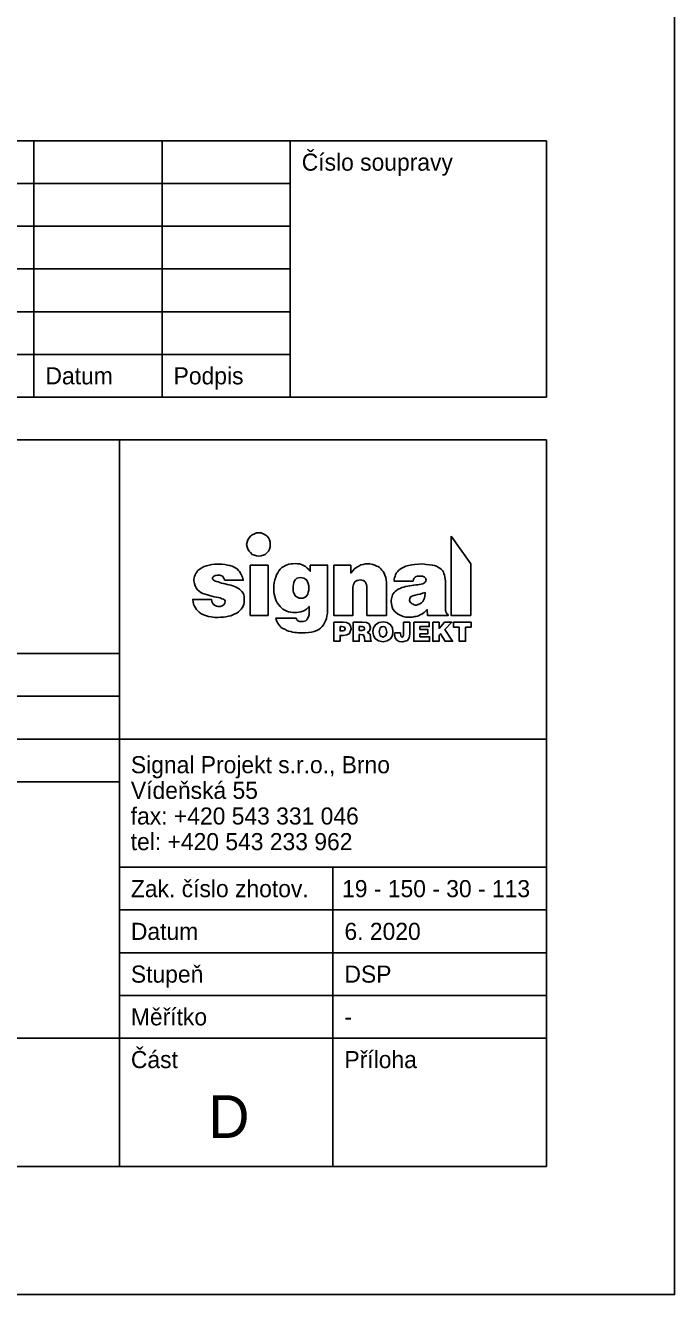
# Model space of a CAD drawing. Extents: x -790471 to -790261, y -985854 to -985557.
# Drawn here: x -790336.6 to -790260.6, y -985853.6 to -985705.1 of the extents above; entities that cross this region are included whole.
import ezdxf

# ---------------------------------------------------------------- set-up
doc = ezdxf.new("R2010")
doc.units = 0
for name, color, linetype in [('Info o rozpiskách', 7, 'Continuous'), ('popis', 7, 'Continuous'), ('Ramečky', 7, 'Continuous'), ('Rámečky-tisk', 7, 'Continuous'), ('Text', 7, 'Continuous'), ('Text barevný', 7, 'Continuous')]:
    doc.layers.add(name, color=color, linetype=linetype)

msp = doc.modelspace()

# ---------------------------------------------------------------- linework, layer by layer
at = {"layer": 'Info o rozpiskách'}
for points in [[(-790309.25, -985764.46), (-790308.98, -985764.47), (-790308.76, -985764.57), (-790308.54, -985764.7), (-790308.29, -985764.87), (-790308.15, -985765.07), (-790308.03, -985765.31), (-790307.94, -985765.58), (-790307.92, -985765.84), (-790307.94, -985766.1), (-790308.03, -985766.38), (-790308.15, -985766.62), (-790308.29, -985766.79), (-790308.54, -985766.99), (-790308.76, -985767.09), (-790308.98, -985767.18), (-790309.25, -985767.2), (-790309.54, -985767.18), (-790309.79, -985767.09), (-790310.05, -985766.99), (-790310.23, -985766.79), (-790310.4, -985766.62), (-790310.57, -985766.38), (-790310.65, -985766.1), (-790310.7, -985765.84), (-790310.65, -985765.58), (-790310.57, -985765.31), (-790310.4, -985765.07), (-790310.23, -985764.87), (-790310.05, -985764.7), (-790309.79, -985764.57), (-790309.54, -985764.47), (-790309.25, -985764.46)], [(-790300.48, -985774.94), (-790299.41, -985774.94), (-790299, -985774.98), (-790298.7, -985775.13), (-790298.52, -985775.37), (-790298.46, -985775.72), (-790298.65, -985776.25), (-790298.95, -985776.42), (-790299.38, -985776.47), (-790299.75, -985776.47), (-790299.75, -985777.16), (-790300.48, -985777.16), (-790300.48, -985774.94)], [(-790299.75, -985775.44), (-790299.75, -985775.95), (-790299.43, -985775.95), (-790299.25, -985775.89), (-790299.15, -985775.69), (-790299.23, -985775.52), (-790299.54, -985775.44), (-790299.75, -985775.44)], [(-790298.24, -985774.94), (-790297.16, -985774.94), (-790296.67, -985774.98), (-790296.35, -985775.13), (-790296.19, -985775.58), (-790296.3, -985775.93), (-790296.56, -985776.12), (-790296.24, -985776.34), (-790296.19, -985776.71), (-790296.19, -985776.88), (-790296.17, -985777.05), (-790296.11, -985777.11), (-790296.11, -985777.16), (-790296.86, -985777.16), (-790296.9, -985776.77), (-790297.03, -985776.42), (-790297.18, -985776.4), (-790297.4, -985776.38), (-790297.51, -985776.38), (-790297.51, -985777.16), (-790298.24, -985777.16), (-790298.24, -985774.94)], [(-790297.51, -985775.44), (-790297.51, -985775.89), (-790297.19, -985775.89), (-790296.93, -985775.82), (-790296.88, -985775.69), (-790296.95, -985775.52), (-790297.16, -985775.44), (-790297.51, -985775.44)], [(-790294.73, -985774.89), (-790294.23, -985774.96), (-790293.84, -985775.22), (-790293.63, -985775.59), (-790293.56, -985776.02), (-790293.63, -985776.49), (-790293.85, -985776.86), (-790294.23, -985777.12), (-790294.73, -985777.22), (-790295.25, -985777.12), (-790295.65, -985776.84), (-790295.83, -985776.47), (-790295.91, -985776.02), (-790295.83, -985775.58), (-790295.61, -985775.22), (-790295.23, -985774.96), (-790294.73, -985774.89)], [(-790294.73, -985775.43), (-790294.92, -985775.46), (-790295.05, -985775.58), (-790295.16, -985776.04), (-790295.05, -985776.53), (-790294.73, -985776.68), (-790294.38, -985776.49), (-790294.28, -985776.08), (-790294.4, -985775.61), (-790294.53, -985775.46), (-790294.73, -985775.43)], [(-790292.33, -985774.94), (-790291.6, -985774.94), (-790291.6, -985776.32), (-790291.67, -985776.75), (-790291.88, -985777.05), (-790292.46, -985777.22), (-790292.83, -985777.18), (-790293.11, -985777.03), (-790293.29, -985776.75), (-790293.37, -985776.36), (-790293.35, -985776.19), (-790292.7, -985776.19), (-790292.66, -985776.56), (-790292.51, -985776.68), (-790292.38, -985776.6), (-790292.33, -985776.42), (-790292.33, -985774.94)], [(-790291.13, -985774.94), (-790289.32, -985774.94), (-790289.32, -985775.44), (-790290.4, -985775.44), (-790290.4, -985775.78), (-790289.49, -985775.78), (-790289.49, -985776.3), (-790290.4, -985776.3), (-790290.4, -985776.64), (-790289.27, -985776.64), (-790289.27, -985777.16), (-790291.13, -985777.16), (-790291.13, -985774.94)], [(-790288.91, -985774.94), (-790288.16, -985774.94), (-790288.16, -985775.65), (-790287.53, -985774.94), (-790286.67, -985774.94), (-790287.49, -985775.78), (-790286.58, -985777.16), (-790287.46, -985777.16), (-790288, -985776.28), (-790288.16, -985776.45), (-790288.16, -985777.16), (-790288.91, -985777.16), (-790288.91, -985774.94)], [(-790286.47, -985774.94), (-790284.41, -985774.94), (-790284.41, -985775.52), (-790285.07, -985775.52), (-790285.07, -985777.16), (-790285.8, -985777.16), (-790285.8, -985775.52), (-790286.47, -985775.52), (-790286.47, -985774.94)]]:
    msp.add_lwpolyline(points, dxfattribs=at)
at = {"layer": 'popis'}
for points in [[(-790286.77, -985764.87), (-790286.77, -985774.14), (-790284.45, -985774.14), (-790284.45, -985768.11), (-790286.77, -985764.87)], [(-790313.29, -985770.02), (-790311.09, -985770.02), (-790311.15, -985769.83), (-790311.19, -985769.66), (-790311.24, -985769.49), (-790311.32, -985769.33), (-790311.41, -985769.18), (-790311.52, -985769.01), (-790311.63, -985768.86), (-790311.8, -985768.69), (-790311.97, -985768.6), (-790312.17, -985768.49), (-790312.4, -985768.39), (-790312.66, -985768.3), (-790312.94, -985768.24), (-790313.26, -985768.19), (-790313.61, -985768.15), (-790314, -985768.13), (-790314.4, -985768.15), (-790314.77, -985768.19), (-790315.09, -985768.26), (-790315.4, -985768.32), (-790315.66, -985768.41), (-790315.89, -985768.52), (-790316.07, -985768.65), (-790316.26, -985768.78), (-790316.43, -985768.93), (-790316.54, -985769.08), (-790316.65, -985769.23), (-790316.71, -985769.4), (-790316.78, -985769.59), (-790316.82, -985769.75), (-790316.86, -985769.89), (-790316.86, -985770.09), (-790316.8, -985770.39), (-790316.71, -985770.69), (-790316.62, -985770.91), (-790316.43, -985771.15), (-790316.26, -985771.28), (-790316.06, -985771.45), (-790315.81, -985771.56), (-790315.55, -985771.64), (-790315.29, -985771.73), (-790315.03, -985771.81), (-790314.77, -985771.88), (-790314.51, -985771.96), (-790314.25, -985771.99), (-790314.02, -985772.03), (-790313.8, -985772.09), (-790313.59, -985772.18), (-790313.39, -985772.25), (-790313.29, -985772.33), (-790313.22, -985772.42), (-790313.2, -985772.52), (-790313.24, -985772.68), (-790313.29, -985772.76), (-790313.33, -985772.85), (-790313.44, -985772.93), (-790313.57, -985773), (-790313.67, -985773.04), (-790313.8, -985773.08), (-790313.93, -985773.08), (-790314.06, -985773.08), (-790314.21, -985773.04), (-790314.38, -985772.98), (-790314.47, -985772.93), (-790314.6, -985772.8), (-790314.69, -985772.68), (-790314.77, -985772.5), (-790314.82, -985772.27), (-790317.01, -985772.27), (-790316.97, -985772.57), (-790316.9, -985772.83), (-790316.8, -985773.06), (-790316.69, -985773.24), (-790316.56, -985773.43), (-790316.41, -985773.6), (-790316.24, -985773.77), (-790316.06, -985773.9), (-790315.83, -985774.01), (-790315.61, -985774.12), (-790315.38, -985774.2), (-790315.14, -985774.27), (-790314.86, -985774.29), (-790314.62, -985774.34), (-790314.38, -985774.36), (-790314.06, -985774.36), (-790313.74, -985774.34), (-790313.43, -985774.34), (-790313.13, -985774.29), (-790312.83, -985774.23), (-790312.55, -985774.18), (-790312.31, -985774.08), (-790312.06, -985773.95), (-790311.86, -985773.86), (-790311.65, -985773.73), (-790311.47, -985773.56), (-790311.34, -985773.41), (-790311.2, -985773.24), (-790311.09, -985773.06), (-790311.02, -985772.83), (-790311, -985772.61), (-790311, -985772.39), (-790311, -985772.33), (-790311, -985772.27), (-790311, -985772.22), (-790311, -985772.16), (-790311, -985772.09), (-790311, -985772.03), (-790311, -985771.99), (-790311, -985771.96), (-790311.02, -985771.71), (-790311.11, -985771.53), (-790311.24, -985771.34), (-790311.39, -985771.21), (-790311.54, -985771.08), (-790311.73, -985770.93), (-790311.9, -985770.84), (-790312.12, -985770.76), (-790312.32, -985770.69), (-790312.55, -985770.61), (-790312.77, -985770.54), (-790312.98, -985770.5), (-790313.22, -985770.44), (-790313.43, -985770.39), (-790313.65, -985770.35), (-790313.84, -985770.3), (-790314.02, -985770.22), (-790314.19, -985770.18), (-790314.32, -985770.11), (-790314.45, -985770.07), (-790314.53, -985770.02), (-790314.64, -985769.94), (-790314.67, -985769.89), (-790314.67, -985769.81), (-790314.67, -985769.74), (-790314.64, -985769.66), (-790314.56, -985769.59), (-790314.49, -985769.55), (-790314.41, -985769.47), (-790314.28, -985769.47), (-790314.13, -985769.44), (-790314, -985769.44), (-790313.85, -985769.44), (-790313.72, -985769.47), (-790313.61, -985769.49), (-790313.5, -985769.55), (-790313.43, -985769.64), (-790313.39, -985769.74), (-790313.31, -985769.85), (-790313.29, -985770.02)], [(-790303.24, -985768.24), (-790303.24, -985768.97), (-790303.41, -985768.77), (-790303.59, -985768.6), (-790303.8, -985768.43), (-790304.04, -985768.28), (-790304.28, -985768.17), (-790304.51, -985768.11), (-790304.75, -985768.08), (-790305.03, -985768.06), (-790305.29, -985768.08), (-790305.48, -985768.09), (-790305.74, -985768.13), (-790305.93, -985768.23), (-790306.15, -985768.28), (-790306.35, -985768.43), (-790306.58, -985768.54), (-790306.76, -985768.73), (-790306.91, -985768.92), (-790307.06, -985769.16), (-790307.19, -985769.4), (-790307.29, -985769.64), (-790307.4, -985769.96), (-790307.47, -985770.3), (-790307.51, -985770.67), (-790307.51, -985771.06), (-790307.51, -985771.38), (-790307.47, -985771.66), (-790307.4, -985771.92), (-790307.32, -985772.2), (-790307.23, -985772.44), (-790307.1, -985772.68), (-790306.93, -985772.89), (-790306.78, -985773.08), (-790306.62, -985773.24), (-790306.45, -985773.39), (-790306.22, -985773.52), (-790306, -985773.62), (-790305.78, -985773.71), (-790305.53, -985773.77), (-790305.29, -985773.8), (-790305.03, -985773.8), (-790304.81, -985773.8), (-790304.6, -985773.77), (-790304.34, -985773.73), (-790304.12, -985773.64), (-790303.91, -985773.54), (-790303.7, -985773.41), (-790303.56, -985773.28), (-790303.39, -985773.09), (-790303.39, -985773.64), (-790303.39, -985774.03), (-790303.46, -985774.29), (-790303.56, -985774.49), (-790303.63, -985774.64), (-790303.76, -985774.75), (-790303.91, -985774.79), (-790304.08, -985774.85), (-790304.26, -985774.85), (-790304.36, -985774.85), (-790304.49, -985774.83), (-790304.6, -985774.79), (-790304.69, -985774.75), (-790304.75, -985774.68), (-790304.84, -985774.61), (-790304.86, -985774.53), (-790304.9, -985774.44), (-790307.27, -985774.44), (-790307.21, -985774.74), (-790307.1, -985774.94), (-790306.97, -985775.17), (-790306.84, -985775.33), (-790306.67, -985775.54), (-790306.45, -985775.65), (-790306.24, -985775.74), (-790306, -985775.89), (-790305.78, -985775.97), (-790305.53, -985776.02), (-790305.31, -985776.08), (-790305.05, -985776.14), (-790304.84, -985776.15), (-790304.66, -985776.17), (-790304.43, -985776.19), (-790304.26, -985776.19), (-790303.85, -985776.17), (-790303.46, -985776.14), (-790303.09, -985776.08), (-790302.79, -985776.01), (-790302.49, -985775.91), (-790302.23, -985775.78), (-790302.03, -985775.63), (-790301.86, -985775.44), (-790301.69, -985775.24), (-790301.56, -985775.02), (-790301.45, -985774.77), (-790301.35, -985774.49), (-790301.32, -985774.2), (-790301.22, -985773.86), (-790301.22, -985773.51), (-790301.22, -985773.09), (-790301.22, -985768.24), (-790303.24, -985768.24)], [(-790300.5, -985768.26), (-790300.5, -985774.14), (-790298.26, -985774.14), (-790298.26, -985771.14), (-790298.26, -985770.82), (-790298.2, -985770.52), (-790298.11, -985770.35), (-790298.03, -985770.2), (-790297.9, -985770.11), (-790297.75, -985770.03), (-790297.57, -985770.02), (-790297.38, -985769.98), (-790297.19, -985770.02), (-790297.06, -985770.05), (-790296.9, -985770.11), (-790296.8, -985770.22), (-790296.73, -985770.35), (-790296.65, -985770.52), (-790296.62, -985770.78), (-790296.62, -985771.04), (-790296.62, -985774.14), (-790294.34, -985774.14), (-790294.34, -985770.59), (-790294.34, -985770.28), (-790294.36, -985769.98), (-790294.41, -985769.7), (-790294.51, -985769.44), (-790294.6, -985769.21), (-790294.71, -985769.01), (-790294.88, -985768.84), (-790294.99, -985768.67), (-790295.14, -985768.54), (-790295.31, -985768.41), (-790295.5, -985768.36), (-790295.68, -985768.26), (-790295.91, -985768.19), (-790296.09, -985768.15), (-790296.28, -985768.11), (-790296.5, -985768.11), (-790296.78, -985768.11), (-790297.06, -985768.19), (-790297.31, -985768.23), (-790297.57, -985768.36), (-790297.81, -985768.49), (-790298.05, -985768.67), (-790298.26, -985768.92), (-790298.5, -985769.18), (-790298.5, -985768.26), (-790300.5, -985768.26)], [(-790293.41, -985770.11), (-790291.19, -985770.11), (-790291.17, -985769.94), (-790291.13, -985769.81), (-790291.06, -985769.72), (-790290.96, -985769.64), (-790290.85, -985769.57), (-790290.7, -985769.53), (-790290.57, -985769.53), (-790290.42, -985769.53), (-790290.25, -985769.53), (-790290.09, -985769.55), (-790289.96, -985769.62), (-790289.88, -985769.66), (-790289.81, -985769.74), (-790289.73, -985769.81), (-790289.73, -985769.9), (-790289.69, -985770), (-790289.73, -985770.09), (-790289.75, -985770.2), (-790289.84, -985770.28), (-790289.94, -985770.35), (-790290.07, -985770.43), (-790290.25, -985770.46), (-790290.46, -985770.5), (-790290.66, -985770.54), (-790290.89, -985770.56), (-790291.13, -985770.59), (-790291.36, -985770.63), (-790291.6, -985770.67), (-790291.84, -985770.73), (-790292.08, -985770.76), (-790292.29, -985770.84), (-790292.51, -985770.87), (-790292.74, -985770.97), (-790292.96, -985771.08), (-790293.15, -985771.23), (-790293.31, -985771.32), (-790293.44, -985771.47), (-790293.54, -985771.62), (-790293.61, -985771.71), (-790293.67, -985771.88), (-790293.7, -985772.03), (-790293.74, -985772.2), (-790293.76, -985772.35), (-790293.76, -985772.52), (-790293.7, -985773), (-790293.56, -985773.39), (-790293.31, -985773.73), (-790293.05, -985773.93), (-790292.74, -985774.12), (-790292.38, -985774.25), (-790292.06, -985774.33), (-790291.73, -985774.34), (-790291.58, -985774.34), (-790291.45, -985774.33), (-790291.3, -985774.33), (-790291.13, -985774.29), (-790291.02, -985774.27), (-790290.85, -985774.25), (-790290.7, -985774.21), (-790290.57, -985774.18), (-790290.44, -985774.1), (-790290.31, -985774.03), (-790290.18, -985773.97), (-790290.03, -985773.88), (-790289.92, -985773.78), (-790289.81, -985773.67), (-790289.66, -985773.56), (-790289.55, -985773.47), (-790289.51, -985774.16), (-790287.12, -985774.16), (-790287.12, -985774.06), (-790287.25, -985773.93), (-790287.31, -985773.84), (-790287.36, -985773.75), (-790287.36, -985773.67), (-790287.4, -985773.56), (-790287.4, -985773.49), (-790287.4, -985773.37), (-790287.4, -985773.23), (-790287.4, -985770.35), (-790287.4, -985770.11), (-790287.46, -985769.87), (-790287.49, -985769.64), (-790287.53, -985769.42), (-790287.59, -985769.23), (-790287.64, -985769.08), (-790287.74, -985768.92), (-790287.9, -985768.75), (-790288.07, -985768.62), (-790288.24, -985768.51), (-790288.46, -985768.39), (-790288.71, -985768.3), (-790288.97, -985768.24), (-790289.3, -985768.21), (-790289.66, -985768.17), (-790290.07, -985768.11), (-790290.53, -985768.13), (-790291.02, -985768.17), (-790291.37, -985768.23), (-790291.73, -985768.28), (-790292.05, -985768.37), (-790292.29, -985768.47), (-790292.53, -985768.6), (-790292.74, -985768.73), (-790292.92, -985768.88), (-790293.05, -985769.03), (-790293.2, -985769.2), (-790293.28, -985769.38), (-790293.31, -985769.53), (-790293.37, -985769.72), (-790293.41, -985769.9), (-790293.41, -985770.11)], [(-790310.27, -985768.26), (-790310.27, -985774.14), (-790308.18, -985774.14), (-790308.18, -985768.26), (-790310.27, -985768.26)], [(-790304.39, -985769.7), (-790304.19, -985769.74), (-790303.98, -985769.79), (-790303.8, -985769.89), (-790303.65, -985770.02), (-790303.56, -985770.2), (-790303.48, -985770.41), (-790303.41, -985770.67), (-790303.41, -985770.95), (-790303.41, -985771.19), (-790303.48, -985771.42), (-790303.54, -985771.64), (-790303.63, -985771.81), (-790303.74, -985771.92), (-790303.91, -985772.05), (-790304.08, -985772.11), (-790304.3, -985772.12), (-790304.53, -985772.11), (-790304.71, -985772.05), (-790304.9, -985771.92), (-790305.01, -985771.83), (-790305.1, -985771.64), (-790305.2, -985771.47), (-790305.23, -985771.25), (-790305.25, -985771.01), (-790305.23, -985770.74), (-790305.2, -985770.5), (-790305.16, -985770.28), (-790305.09, -985770.07), (-790304.99, -985769.94), (-790304.82, -985769.79), (-790304.64, -985769.74), (-790304.39, -985769.7)], [(-790289.81, -985771.47), (-790289.81, -985771.49), (-790289.81, -985771.55), (-790289.81, -985771.58), (-790289.84, -985771.84), (-790289.86, -985772.11), (-790289.96, -985772.29), (-790290.07, -985772.52), (-790290.22, -985772.68), (-790290.4, -985772.78), (-790290.61, -985772.87), (-790290.81, -985772.93), (-790290.98, -985772.93), (-790291.09, -985772.89), (-790291.21, -985772.83), (-790291.32, -985772.78), (-790291.43, -985772.7), (-790291.52, -985772.61), (-790291.6, -985772.52), (-790291.62, -985772.37), (-790291.58, -985772.12), (-790291.45, -985771.94), (-790291.22, -985771.83), (-790290.98, -985771.75), (-790290.66, -985771.68), (-790290.38, -985771.64), (-790290.09, -985771.55), (-790289.81, -985771.47)]]:
    msp.add_lwpolyline(points, dxfattribs=at)
at = {"layer": 'Ramečky'}
for p, q in [((-790275.59, -985718.6), (-790455.59, -985718.6)), ((-790335.59, -985718.6), (-790335.59, -985748.6)), ((-790320.59, -985718.6), (-790320.59, -985748.6)), ((-790305.59, -985718.6), (-790305.59, -985748.6)), ((-790275.59, -985718.6), (-790275.59, -985748.6)), ((-790305.59, -985723.6), (-790455.59, -985723.6)), ((-790305.59, -985728.6), (-790455.59, -985728.6)), ((-790305.59, -985733.6), (-790455.59, -985733.6)), ((-790305.59, -985738.6), (-790455.59, -985738.6)), ((-790305.59, -985743.6), (-790455.59, -985743.6)), ((-790275.59, -985748.6), (-790455.59, -985748.6)), ((-790275.59, -985753.6), (-790455.59, -985753.6)), ((-790325.59, -985838.6), (-790325.59, -985753.6)), ((-790275.59, -985838.6), (-790275.59, -985753.6)), ((-790455.59, -985778.6), (-790325.59, -985778.6)), ((-790455.59, -985783.6), (-790325.59, -985783.6)), ((-790455.59, -985788.6), (-790325.59, -985788.6)), ((-790455.59, -985793.6), (-790325.59, -985793.6)), ((-790325.59, -985803.6), (-790275.59, -985803.6)), ((-790325.59, -985808.6), (-790275.59, -985808.6)), ((-790325.59, -985813.6), (-790275.59, -985813.6)), ((-790325.59, -985818.6), (-790275.59, -985818.6)), ((-790455.59, -985823.6), (-790275.59, -985823.6)), ((-790455.59, -985838.6), (-790275.59, -985838.6))]:
    msp.add_line(p, q, dxfattribs=at)
for points in [[(-790325.59, -985788.6), (-790275.59, -985788.6)], [(-790300.59, -985803.6), (-790300.59, -985838.6)]]:
    msp.add_lwpolyline(points, dxfattribs=at)
at = {"layer": 'Rámečky-tisk'}
msp.add_lwpolyline([(-790470.59, -985853.6), (-790260.59, -985853.6), (-790260.59, -985556.6)], dxfattribs=at)

# ---------------------------------------------------------------- texts
at = {"layer": 'Text'}
for s, p in [('Číslo soupravy', (-790304.24, -985722.1)), ('Datum', (-790334.24, -985747.1)), ('Podpis', (-790319.24, -985747.1)), ('Signal Projekt s.r.o., Brno', (-790324.24, -985792.6)), ('Vídeňská 55', (-790324.24, -985795.6)), ('fax: +420 543 331 046', (-790324.26, -985798.6)), ('tel: +420 543 233 962', (-790324.26, -985801.6)), ('Zak. číslo zhotov.', (-790324.24, -985807.1)), ('19 - 150 - 30 - 113', (-790299.52, -985807.1)), ('Datum', (-790324.24, -985812.1)), ('6. 2020', (-790299.24, -985812.1)), ('Stupeň', (-790324.24, -985817.1)), ('DSP', (-790299.24, -985817.1)), ('Měřítko', (-790324.24, -985822.1)), ('-', (-790299.24, -985822.1)), ('Část', (-790324.24, -985827.1)), ('Příloha', (-790299.24, -985827.1))]:
    msp.add_text(s, height=2, dxfattribs=at).set_placement(p)
at = {"layer": 'Text barevný'}
msp.add_text('D', height=5, dxfattribs=at).set_placement((-790315.19, -985835.27))

doc.saveas('drawing.dxf')
